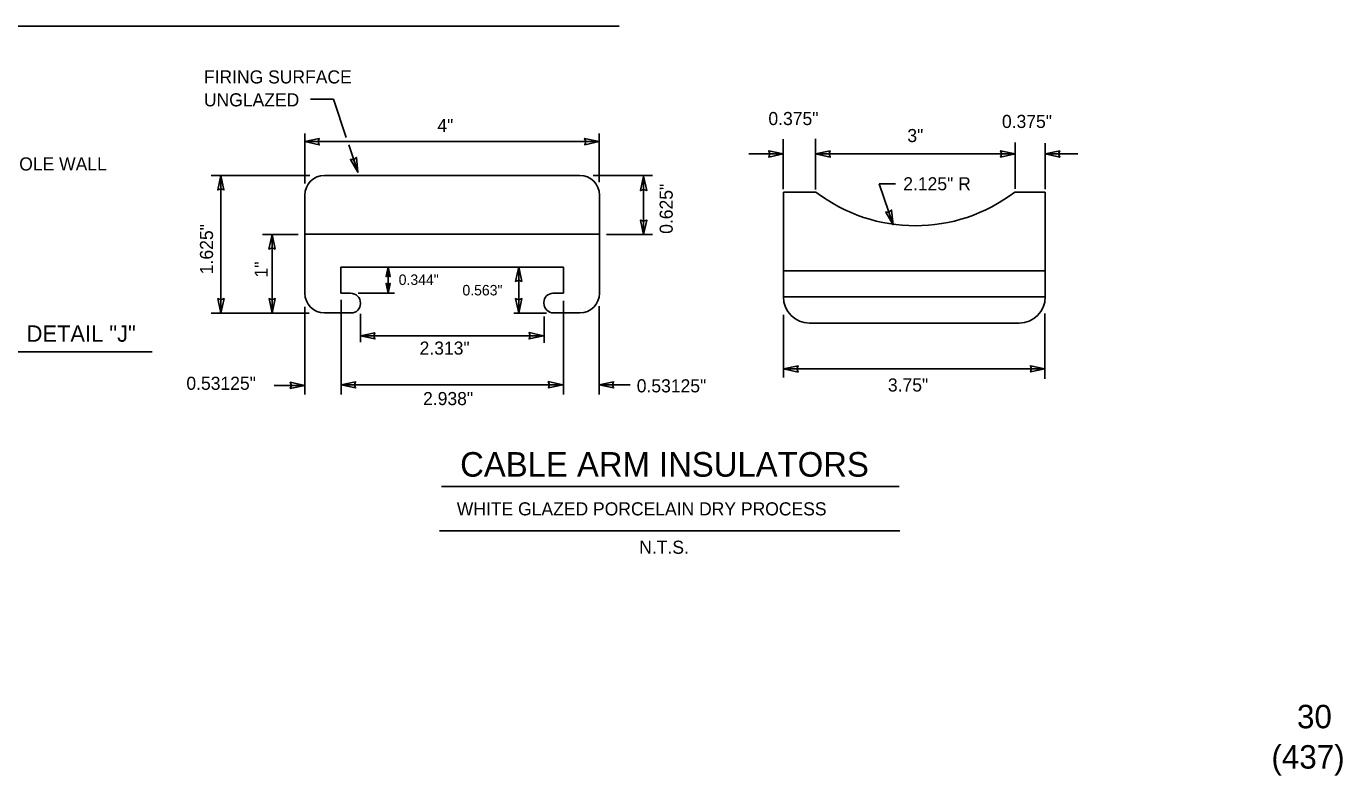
# Model space of a CAD drawing. Extents: x 19188 to 19495, y 20866 to 21061.
# Drawn here: x 19410.8 to 19495, y 20865.8 to 20913.8 of the extents above; entities that cross this region are included whole.
import ezdxf

# ---------------------------------------------------------------- set-up
doc = ezdxf.new("R2010")
doc.units = 0
doc.layers.add('G-ANNO-NOTE', color=7, linetype='Continuous')
doc.layers.add('G-ANNO-TTLB', color=7, linetype='Continuous')

msp = doc.modelspace()

# ---------------------------------------------------------------- linework, layer by layer
at = {"layer": 'G-ANNO-NOTE'}
for p, q in [((19403.002, 20913.752), (19448.727, 20913.752)), ((19428.973, 20909.101), (19430.451, 20909.101)), ((19430.451, 20909.101), (19431.27, 20906.651)), ((19428.612, 20903.69), (19428.612, 20906.904)), ((19447.449, 20903.779), (19447.449, 20906.904)), ((19459.23, 20903.344), (19459.23, 20906.538)), ((19461.302, 20903.322), (19461.302, 20906.56)), ((19428.612, 20906.376), (19447.449, 20906.376)), ((19428.612, 20906.376), (19429.465, 20906.376)), ((19432.016, 20904.423), (19431.433, 20906.167)), ((19447.449, 20906.376), (19446.596, 20906.376)), ((19474.06, 20903.365), (19474.06, 20906.327)), ((19475.996, 20903.344), (19475.996, 20906.284)), ((19432.016, 20904.423), (19431.745, 20905.232)), ((19459.23, 20905.587), (19457.02, 20905.587)), ((19459.23, 20905.587), (19458.376, 20905.587)), ((19461.302, 20905.587), (19474.06, 20905.587)), ((19461.302, 20905.587), (19462.156, 20905.587)), ((19474.06, 20905.587), (19473.207, 20905.587)), ((19475.996, 20905.587), (19478.069, 20905.587)), ((19475.996, 20905.587), (19476.849, 20905.587)), ((19428.944, 20904.219), (19422.633, 20904.219)), ((19423.25, 20895.411), (19423.25, 20904.219)), ((19423.25, 20904.219), (19423.25, 20903.366)), ((19429.874, 20904.218), (19446.212, 20904.218)), ((19447.069, 20904.219), (19450.865, 20904.219)), ((19450.296, 20900.432), (19450.296, 20904.175)), ((19450.296, 20904.175), (19450.296, 20903.322)), ((19459.238, 20903.148), (19461.32, 20903.148)), ((19459.238, 20896.445), (19459.238, 20903.148)), ((19466.405, 20903.682), (19465.358, 20903.682)), ((19465.358, 20903.682), (19466.269, 20901.06)), ((19475.994, 20903.148), (19474.038, 20903.148)), ((19475.994, 20896.445), (19475.994, 20903.148)), ((19428.618, 20902.961), (19428.618, 20896.677)), ((19447.47, 20902.961), (19447.47, 20896.677)), ((19466.269, 20901.06), (19465.989, 20901.866)), ((19450.296, 20900.432), (19450.296, 20901.284)), ((19428.185, 20900.432), (19425.908, 20900.432)), ((19426.524, 20900.432), (19426.524, 20895.411)), ((19426.524, 20900.432), (19426.524, 20899.579)), ((19428.618, 20900.448), (19447.47, 20900.448)), ((19447.923, 20900.432), (19450.865, 20900.432)), ((19430.922, 20896.677), (19430.922, 20898.353)), ((19430.922, 20898.353), (19445.165, 20898.353)), ((19433.95, 20896.688), (19433.95, 20898.362)), ((19433.95, 20898.362), (19433.95, 20897.793)), ((19442.301, 20895.411), (19442.301, 20898.362)), ((19442.301, 20898.362), (19442.301, 20897.509)), ((19445.165, 20896.677), (19445.165, 20898.353)), ((19459.207, 20898.121), (19475.951, 20898.121)), ((19433.95, 20896.688), (19433.95, 20897.257)), ((19431.55, 20896.677), (19430.922, 20896.677)), ((19432.028, 20896.688), (19434.353, 20896.688)), ((19444.495, 20896.677), (19445.165, 20896.677)), ((19459.238, 20896.445), (19475.994, 20896.445)), ((19423.25, 20895.411), (19423.25, 20896.264)), ((19426.524, 20895.411), (19426.524, 20896.264)), ((19428.612, 20895.807), (19428.612, 20890.212)), ((19430.937, 20896.248), (19430.937, 20890.212)), ((19432.179, 20896.007), (19432.179, 20896.049)), ((19442.301, 20895.411), (19442.301, 20896.264)), ((19443.908, 20896.049), (19443.908, 20896.091)), ((19445.171, 20896.204), (19445.171, 20890.212)), ((19447.449, 20895.851), (19447.449, 20890.212)), ((19428.896, 20895.411), (19422.633, 20895.411)), ((19429.874, 20895.421), (19431.592, 20895.421)), ((19432.17, 20895.367), (19432.17, 20893.561)), ((19444.079, 20895.411), (19441.992, 20895.411)), ((19443.937, 20895.19), (19443.937, 20893.517)), ((19446.212, 20895.421), (19444.537, 20895.421)), ((19459.252, 20895.308), (19459.252, 20891.291)), ((19460.913, 20894.769), (19474.319, 20894.769)), ((19475.974, 20895.393), (19475.974, 20891.206)), ((19432.17, 20893.957), (19443.89, 20893.957)), ((19432.17, 20893.957), (19433.023, 20893.957)), ((19443.89, 20893.957), (19443.037, 20893.957)), ((19409.82, 20892.93), (19418.843, 20892.93)), ((19459.252, 20891.841), (19475.974, 20891.841)), ((19459.252, 20891.841), (19460.105, 20891.841)), ((19475.974, 20891.841), (19475.12, 20891.841)), ((19428.612, 20890.784), (19426.666, 20890.784)), ((19428.612, 20890.784), (19427.759, 20890.784)), ((19430.937, 20890.829), (19445.123, 20890.829)), ((19430.937, 20890.829), (19431.79, 20890.829)), ((19445.123, 20890.829), (19444.271, 20890.829)), ((19447.449, 20890.829), (19449.442, 20890.829)), ((19447.449, 20890.829), (19448.301, 20890.829)), ((19437.352, 20884.309), (19466.655, 20884.309)), ((19437.237, 20881.487), (19466.693, 20881.487))]:
    msp.add_line(p, q, dxfattribs=at)
for points in [[(19429.465, 20906.376), (19429.54, 20906.172), (19428.612, 20906.376), (19429.538, 20906.57), (19429.465, 20906.376)], [(19446.595, 20906.376), (19446.521, 20906.579), (19447.449, 20906.376), (19446.523, 20906.181), (19446.595, 20906.376)], [(19458.376, 20905.587), (19458.302, 20905.791), (19459.23, 20905.587), (19458.304, 20905.392), (19458.376, 20905.587)], [(19462.156, 20905.587), (19462.23, 20905.383), (19461.302, 20905.587), (19462.228, 20905.782), (19462.156, 20905.587)], [(19473.207, 20905.587), (19473.132, 20905.791), (19474.06, 20905.587), (19473.134, 20905.392), (19473.207, 20905.587)], [(19476.849, 20905.587), (19476.924, 20905.383), (19475.996, 20905.587), (19476.922, 20905.782), (19476.849, 20905.587)], [(19431.745, 20905.232), (19431.915, 20905.368), (19432.016, 20904.423), (19431.538, 20905.239), (19431.745, 20905.232)], [(19423.25, 20903.366), (19423.046, 20903.291), (19423.25, 20904.219), (19423.445, 20903.293), (19423.25, 20903.366)], [(19450.296, 20903.322), (19450.091, 20903.247), (19450.296, 20904.175), (19450.49, 20903.249), (19450.296, 20903.322)], [(19465.989, 20901.866), (19466.157, 20902.003), (19466.269, 20901.06), (19465.781, 20901.87), (19465.989, 20901.866)], [(19450.295, 20901.284), (19450.499, 20901.359), (19450.296, 20900.432), (19450.101, 20901.357), (19450.295, 20901.284)], [(19426.524, 20899.578), (19426.321, 20899.504), (19426.524, 20900.432), (19426.719, 20899.506), (19426.524, 20899.578)], [(19433.95, 20897.793), (19433.814, 20897.743), (19433.95, 20898.362), (19434.08, 20897.745), (19433.95, 20897.793)], [(19442.301, 20897.508), (19442.097, 20897.434), (19442.301, 20898.362), (19442.495, 20897.436), (19442.301, 20897.508)], [(19433.95, 20897.257), (19434.085, 20897.306), (19433.95, 20896.688), (19433.82, 20897.305), (19433.95, 20897.257)], [(19423.25, 20896.264), (19423.454, 20896.339), (19423.25, 20895.411), (19423.055, 20896.337), (19423.25, 20896.264)], [(19426.524, 20896.264), (19426.728, 20896.339), (19426.524, 20895.411), (19426.33, 20896.337), (19426.524, 20896.264)], [(19442.301, 20896.264), (19442.504, 20896.339), (19442.301, 20895.411), (19442.106, 20896.337), (19442.301, 20896.264)], [(19433.023, 20893.958), (19433.098, 20893.754), (19432.17, 20893.957), (19433.096, 20894.152), (19433.023, 20893.958)], [(19443.037, 20893.957), (19442.962, 20894.161), (19443.89, 20893.957), (19442.964, 20893.763), (19443.037, 20893.957)], [(19460.105, 20891.841), (19460.18, 20891.637), (19459.252, 20891.841), (19460.178, 20892.035), (19460.105, 20891.841)], [(19475.12, 20891.841), (19475.046, 20892.044), (19475.974, 20891.841), (19475.048, 20891.646), (19475.12, 20891.841)], [(19427.758, 20890.784), (19427.684, 20890.988), (19428.612, 20890.784), (19427.686, 20890.59), (19427.758, 20890.784)], [(19431.79, 20890.829), (19431.864, 20890.625), (19430.937, 20890.829), (19431.862, 20891.023), (19431.79, 20890.829)], [(19444.27, 20890.829), (19444.196, 20891.032), (19445.123, 20890.829), (19444.198, 20890.634), (19444.27, 20890.829)], [(19448.301, 20890.829), (19448.376, 20890.625), (19447.449, 20890.829), (19448.374, 20891.023), (19448.301, 20890.829)]]:
    msp.add_lwpolyline(points, dxfattribs=at)
for centre, radius, start, end in [((19429.875, 20902.961), 1.257, 90, 179.99999), ((19446.213, 20902.961), 1.257, 0, 90), ((19467.679, 20911.47), 10.473, 232.61529, 307.38471), ((19429.875, 20896.678), 1.257, 180, 269.99999), ((19431.55, 20896.049), 0.628, 0, 90), ((19444.495, 20896.091), 0.586, 90, 179.99999), ((19446.213, 20896.678), 1.257, 270, 0), ((19460.913, 20896.445), 1.676, 180, 269.99999), ((19474.319, 20896.445), 1.676, 270, 0), ((19431.592, 20896.007), 0.586, 270, 0), ((19444.537, 20896.049), 0.628, 180, 269.99999)]:
    msp.add_arc(centre, radius, start, end, dxfattribs=at)

# ---------------------------------------------------------------- texts
for s, height, p in [('FIRING SURFACE', 0.83785, (19422.16, 20910.098)), ('UNGLAZED', 0.8379, (19422.16, 20908.632)), ('0.375"', 0.8379, (19458.279, 20907.436)), ('4"', 0.8379, (19437.097, 20906.992)), ('0.375"', 0.8379, (19473.221, 20907.25)), ('3"', 0.8379, (19467.169, 20906.348)), ('HANDHOLE WALL', 0.83785, (19406.36, 20904.532)), ('2.125" R', 0.8379, (19466.907, 20903.263)), ('0.344"', 0.6703, (19434.624, 20897.211)), ('0.563"', 0.6703, (19438.702, 20896.541)), ('DETAIL "J"', 1.0473, (19410.818, 20893.577)), ('2.313"', 0.8379, (19435.962, 20892.753)), ('0.53125"', 0.8379, (19421.039, 20890.502)), ('0.53125"', 0.8379, (19449.855, 20890.34)), ('3.75"', 0.8379, (19465.924, 20890.395)), ('2.938"', 0.8379, (19436.184, 20889.525)), ('CABLE ARM INSULATORS', 1.57098, (19438.555, 20884.948)), ('WHITE GLAZED PORCELAIN DRY PROCESS', 0.83785, (19438.341, 20882.47)), ('N.T.S.', 0.8379, (19450.015, 20880.017))]:
    msp.add_text(s, height=height, dxfattribs=at).set_placement(p)
for s, p in [('0.625"', (19452.157, 20900.48)), ('1.625"', (19422.745, 20897.899)), ('1"', (19426.241, 20897.685))]:
    msp.add_text(s, height=0.8379, rotation=90, dxfattribs=at).set_placement(p)
at = {"layer": 'G-ANNO-TTLB'}
for s, p in [('30', (19492.098, 20868.855)), ('(437)', (19490.463, 20866.276))]:
    msp.add_text(s, height=1.5, dxfattribs=at).set_placement(p)

doc.saveas('drawing.dxf')
